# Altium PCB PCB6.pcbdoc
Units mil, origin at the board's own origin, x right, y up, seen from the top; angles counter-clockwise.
Board outline 6080 x 3305 mil, 2 copper layers (Top Layer, Bottom Layer); 30 components, 10 nets, 241 pads, 0 vias.
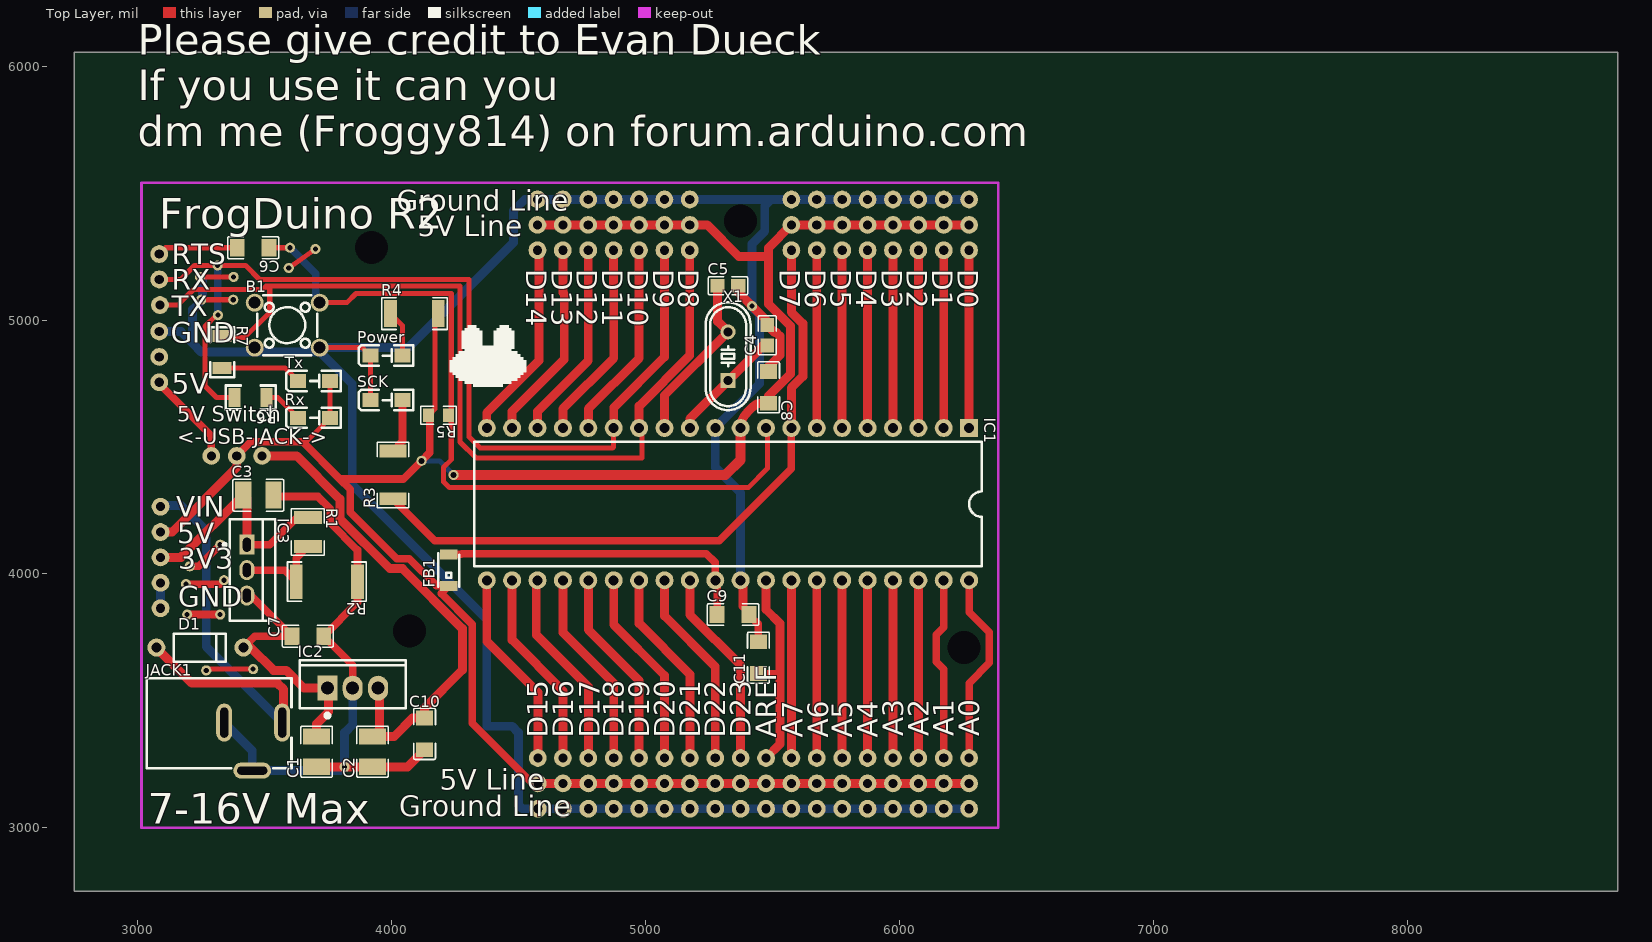
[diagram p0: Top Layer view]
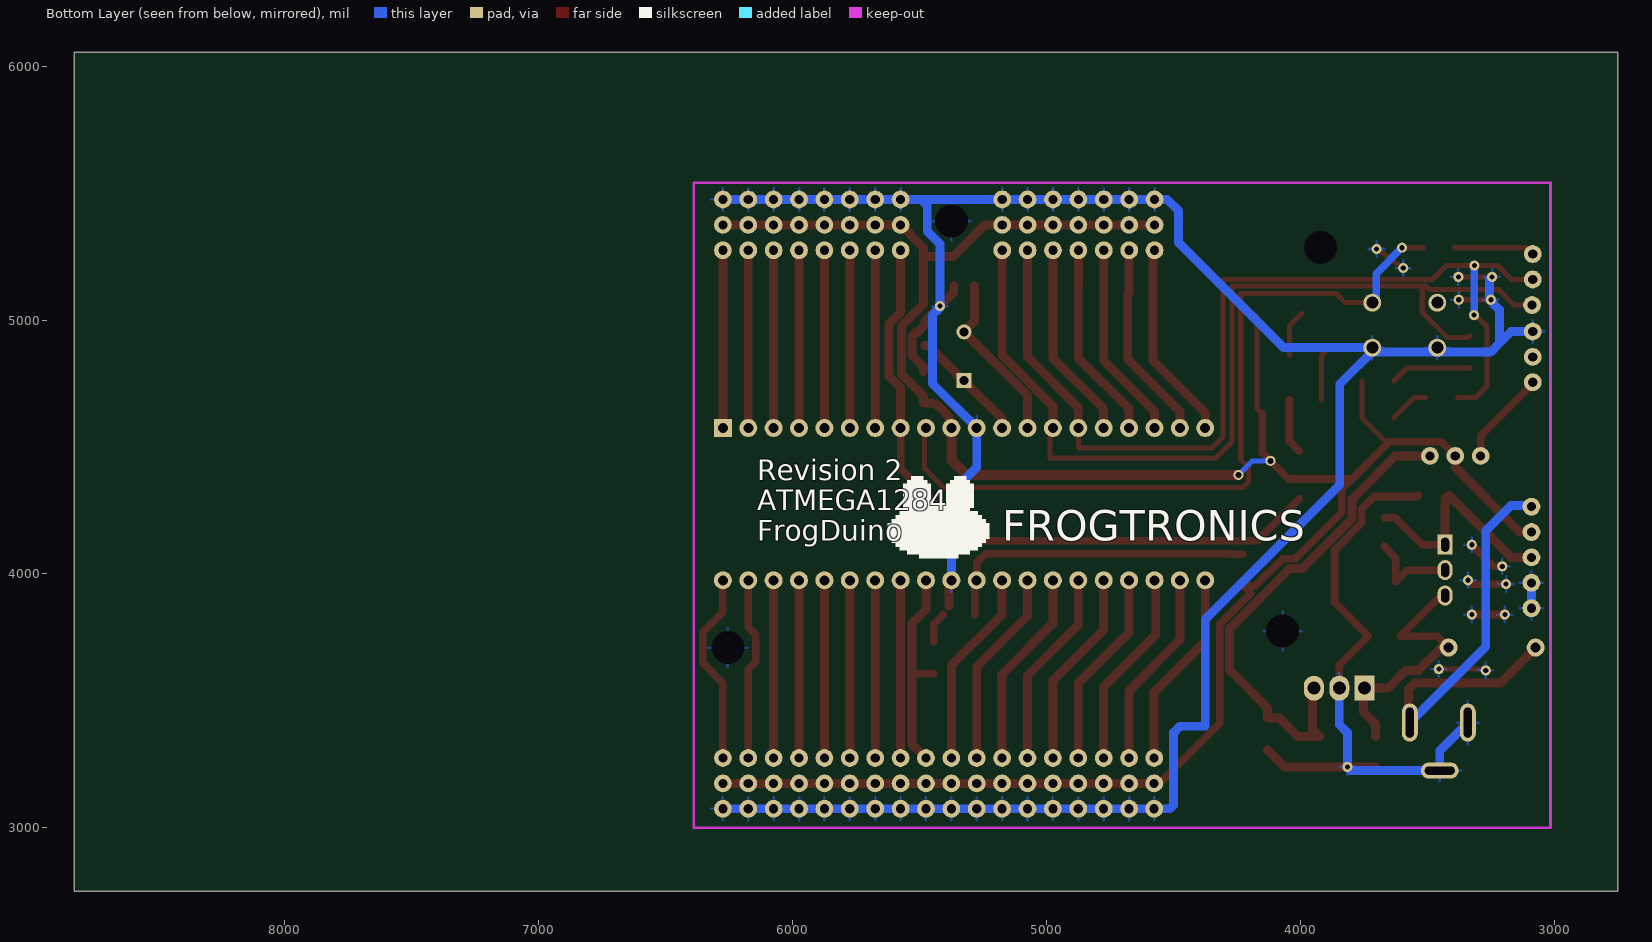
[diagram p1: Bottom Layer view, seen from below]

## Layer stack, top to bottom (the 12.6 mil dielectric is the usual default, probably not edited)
Top Layer: signal copper (thickness not stored)
Dielectric: dielectric 12.6, FR-4, Dk 4.8
Bottom Layer: signal copper (thickness not stored)

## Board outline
8830,2750 2750,2750 2750,6055 8830,6055

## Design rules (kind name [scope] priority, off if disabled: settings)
BoardOutlineClearance copperThickness1oz [All] p0: genericclearance=10 ignorepadtopadclearanceinfootprint=FALSE except(0: Arc-SplitContinuation Track-SplitContinuation SMDPad-SplitContinuation THPad-SplitContinuation Via-SplitContinuation Fill-SplitContinuation Poly-SplitContinuation Region-SplitContinuation Text-SplitContinuation; 6: Track-CutoutEdge SMDPad-CutoutEdge THPad-CutoutEdge Via-CutoutEdge Region-CutoutEdge; 11.8: Track-OutlineEdge SMDPad-OutlineEdge THPad-OutlineEdge Via-OutlineEdge Fill-OutlineEdge Region-OutlineEdge Poly-OutlineEdge Text-OutlineEdge Fill-CutoutEdge)
BoardOutlineClearance copperThickness2oz [All] p0: genericclearance=10 ignorepadtopadclearanceinfootprint=FALSE except(0: Arc-SplitContinuation Track-SplitContinuation SMDPad-SplitContinuation THPad-SplitContinuation Via-SplitContinuation Fill-SplitContinuation Poly-SplitContinuation Region-SplitContinuation Text-SplitContinuation; 6: Track-CutoutEdge SMDPad-CutoutEdge THPad-CutoutEdge Via-CutoutEdge Region-CutoutEdge; 11.8: Track-OutlineEdge SMDPad-OutlineEdge THPad-OutlineEdge Via-OutlineEdge Fill-OutlineEdge Region-OutlineEdge Poly-OutlineEdge Text-OutlineEdge Fill-CutoutEdge)
Clearance copperThickness1oz [(InNet('GROUND') OR InNet('VCC') OR InNet('5VUSB') OR InNet('3V3') OR InNet('XTAL1') OR InNet('XTAL2') OR InNet('AREF') OR InNet('5V') OR InNet('POWER') OR InNet('AVCC'))] p1: gap=7 ignorepadtopadclearanceinfootprint=FALSE except(6: Track-Track Track-SMDPad SMDPad-SMDPad Track-THPad SMDPad-THPad THPad-THPad Track-Via SMDPad-Via THPad-Via Via-Via SMDPad-Fill THPad-Fill Via-Fill Fill-Fill Track-Region SMDPad-Region THPad-Region Via-Region Region-Region Track-Poly SMDPad-Poly THPad-Poly Via-Poly Fill-Poly Region-Poly Poly-Poly Track-Text SMDPad-Text THPad-Text Via-Text Fill-Text Region-Text Poly-Text Text-Text; 6.9: Track-Hole SMDPad-Hole THPad-Hole Via-Hole Fill-Hole Region-Hole Poly-Hole Text-Hole Sheet-Hole; 11.8: Track-Fill Fill-Region Track-Sheet SMDPad-Sheet THPad-Sheet Via-Sheet Fill-Sheet Region-Sheet Poly-Sheet Text-Sheet)
Clearance copperThickness2oz [All] p1: gap=7 ignorepadtopadclearanceinfootprint=FALSE except(6: Track-SMDPad SMDPad-SMDPad Track-THPad SMDPad-THPad THPad-THPad Track-Via SMDPad-Via THPad-Via Via-Via SMDPad-Fill THPad-Fill Via-Fill Fill-Fill Track-Region SMDPad-Region THPad-Region Via-Region Region-Region Track-Poly SMDPad-Poly THPad-Poly Via-Poly Fill-Poly Region-Poly Poly-Poly Track-Text SMDPad-Text THPad-Text Via-Text Fill-Text Region-Text Poly-Text Text-Text; 6.9: Track-Hole SMDPad-Hole THPad-Hole Via-Hole Fill-Hole Region-Hole Poly-Hole Text-Hole Sheet-Hole; 8: Track-Track; 11.8: Track-Fill Fill-Region Track-Sheet SMDPad-Sheet THPad-Sheet Via-Sheet Fill-Sheet Region-Sheet Poly-Sheet Text-Sheet)
DiffPairsRouting differentialPair [All] p1: maxuncoupledlength=10 minlimit=6 maxlimit=6 mostfreqgap=6 toplayer_minwidth=5 toplayer_prefwidth=10 toplayer_maxwidth=100 bottomlayer_minwidth=5 bottomlayer_prefwidth=10 bottomlayer_maxwidth=100
PasteMaskExpansion pasteMaskExpansion [All] p1: expansion=0
PlaneConnect innerPlane [All] p1: planeconnectstyle=Relief reliefexpansion=20 reliefentries=4 reliefconductorwidth=10 reliefairgap=10
PolygonConnect copperRegion [All] p1: connectstyle=Relief reliefentries=4 reliefconductorwidth=10 polygonreliefangle="90 Angle" airgapwidth=10
PolygonConnect copperRegion1 [All] p1: connectstyle=Relief reliefentries=4 reliefconductorwidth=10 polygonreliefangle="90 Angle" airgapwidth=10
PolygonConnect copperRegion2 [All] p1: connectstyle=Relief reliefentries=4 reliefconductorwidth=10 polygonreliefangle="90 Angle" airgapwidth=10
RoutingVias viaSize [All] p1: viastyle="Through Hole" holewidth=20 minholewidth=10 maxholewidth=400 width=40 minwidth=20 maxwidth=600
SolderMaskExpansion solderMaskExpansion [All] p1: useseparateexpansions=TRUE expansion=2 expansionbottom=2
Width copperThickness1oz [All] p1: maxlimit=200 minlimit=10 preferedwidth=20
Width copperThickness2oz [All] p1: maxlimit=100 minlimit=8 preferedwidth=10

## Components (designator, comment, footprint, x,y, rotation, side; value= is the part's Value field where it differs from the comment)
B1 "TS02-66-43-BK-100-SCR-D" SW-TH_4P-L6.0-W6.0-P4.50-LS6.5 3588.99,4979.83 r0 top
C1 "CC1210MKX5R7BB107" C1210 3705,3300 r90 top
C2 "CC1210MKX5R7BB107" C1210 3925,3300 r90 top
C3 "CC1210MKX5R7BB107" C1210 3475,4310 r0 top
C4 "CL21C220JBANNNC" C0805 5480,4940 r90 top
C5 "CL21C220JBANNNC" C0805 5325,5135 r0 top
C6 "1206B104K101CT" C1206 3455,5285 r180 top
C7 "1206B104K101CT" C1206 3670,3755 r180 top
C8 "1206B104K101CT" C1206 5485,4735 r90 top
C9 "1206B104K101CT" C1206 5345,3840 r0 top
C10 "1206B104K101CT" C1206 4130,3370 r90 top
C11 "1206B104K101CT" C1206 5445,3670 r90 top
D1 "1N4007GP-E3/54" DO-41_BD2.4-L4.7-P8.70-D0.9-RD 3245,3710 r180 top
FB1 "2450AT18A100E" ANT-SMD_L3.2-W1.6 4225,4015 r90 top
IC1 "ATMEGA1284-PU" PDIP-40_L52.3-W13.8-P2.54-LS15.2-BL 5325,4275 r180 top
IC2 "LM7805L-TA3-T" TO-220IS_L10.16-W4.7-P2.54-L 3846.95,3550 r0 top
IC3 "LM317T/NOPB" TO-220-3_L10.2-W4.6-P2.54-L 3430,4015 r270 top
JACK1 "694106301002_C5441017" DC-IN-TH_694106301002 3455,3320 r0 top
Power "SML-811UTT86C" LED-SMD_L3.4-W1.3-RD 3980,4860 r0 top
R1 "RC1210FR-07240RL" R1210 3670,4165 r270 top
R2 "CRGP2512F390R" R2512 3745,3970 r180 top
R3 "RC2010JK-07330RL" R2010 4005,4390 r90 top
R4 "RC2010JK-07330RL" R2010 4090,5025 r0 top
R5 "0805W8F1002T5E" R0805 4185,4625 r180 top
R6 "330" R1206 3445,4695 r180 top
R7 "330" R1206 3332.88,4873.95 r270 top
Rx "SML-811UTT86C" LED-SMD_L3.4-W1.3-RD 3695,4615 r0 top
SCK "SML-811UTT86C" LED-SMD_L3.4-W1.3-RD 3980,4685 r0 top
Tx "SML-811UTT86C" LED-SMD_L3.4-W1.3-RD 3695,4760 r0 top
X1 "XIHCELNANF-16MHZ" HC-49US_L11.5-W4.5-P4.88 5325.38,4857.5 r90 top

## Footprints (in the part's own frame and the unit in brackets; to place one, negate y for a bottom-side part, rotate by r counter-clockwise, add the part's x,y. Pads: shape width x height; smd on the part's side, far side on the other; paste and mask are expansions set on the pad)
ANT-SMD_L3.2-W1.6 [mm]
  rect 1x1.75 smd: 1(-1.578,0) 2(1.578,0)
  silkscreen extent -1.68,-1.05 1.68,1.06
C0805 [mm]
  rect 1.41x1.35 smd: 1(-1.03,0) 2(1.03,0)
  silkscreen extent -1.96,-0.9 1.96,0.9
C1206 [mm]
  rect 1.485x1.728 smd: 1(-1.593,0) 2(1.593,0)
  silkscreen extent -2.56,-1.09 2.56,1.09
C1210 [mm]
  rect 1.635x2.7 smd: 1(-1.517,0) 2(1.517,0)
  silkscreen extent -2.56,-1.58 2.56,1.58
DC-IN-TH_694106301002 [mm]
  oval 1.6x3.8 hole 0.8 slot 3 at 90 deg: 1(2.9,2.4)
  oval 1.6x3.8 hole 0.8 slot 3 at 90 deg copper offset 0,0: 2(-2.9,2.4)
  oval 3.8x1.6 hole 0.8 slot 3 at 0 deg: 3(-0.1,-2.4)
  silkscreen extent -10.65,-2.17 3.83,6.84
DO-41_BD2.4-L4.7-P8.70-D0.9-RD [mm]
  round 1.8 hole 1: 1(-4.35,0) 2(4.35,0)
  silkscreen extent -2.6,-1.4 2.6,1.4
HC-49US_L11.5-W4.5-P4.88 [mm]
  rect 1.5x1.5 hole 0.9: 1(-2.44,0)
  round 1.5 hole 0.9: 2(2.44,0)
  silkscreen extent -5.39,-2.25 5.39,2.25
LED-SMD_L3.4-W1.3-RD [mm]
  rect 1.6x1.4 smd: 1(-1.6,0) 2(1.6,0)
  silkscreen extent -2.79,-1.02 2.67,1.02
PDIP-40_L52.3-W13.8-P2.54-LS15.2-BL [mm]
  rect 1.8x1.8 hole 1: 1(-24.13,-7.62)
  round 1.8 hole 1: 2(-21.59,-7.62) 3(-19.05,-7.62) 4(-16.51,-7.62) 5(-13.97,-7.62) 6(-11.43,-7.62) 7(-8.89,-7.62) 8(-6.35,-7.62) 9(-3.81,-7.62) 10(-1.27,-7.62) 11(1.27,-7.62) 12(3.81,-7.62) 13(6.35,-7.62) 14(8.89,-7.62) 15(11.43,-7.62) 16(13.97,-7.62) 17(16.51,-7.62) 18(19.05,-7.62) 19(21.59,-7.62) 20(24.13,-7.62) 21(24.13,7.62) 22(21.59,7.62) 23(19.05,7.62) 24(16.51,7.62) 25(13.97,7.62) 26(11.43,7.62) 27(8.89,7.62) 28(6.35,7.62) 29(3.81,7.62) 30(1.27,7.62) 31(-1.27,7.62) 32(-3.81,7.62) 33(-6.35,7.62) 34(-8.89,7.62) 35(-11.43,7.62) 36(-13.97,7.62) 37(-16.51,7.62) 38(-19.05,7.62) 39(-21.59,7.62) 40(-24.13,7.62)
  silkscreen extent -25.4,-6.22 25.4,6.22
R0805 [mm]
  rect 1.133x1.377 smd: 1(-1,0) 2(1,0)
  silkscreen extent -1.76,-0.92 1.76,0.92
R1206 [mm]
  rect 1.2x1.9 smd: 1(-1.6,0) 2(1.6,0)
  silkscreen extent -2.5,-1.2 2.5,1.2
R1210 [mil]
  rect 50.49x110.55 smd: 1(-56.74,0) 2(56.74,0)
  silkscreen extent -91,-64 91,64
R2010 [mm]
  rect 1.283x2.7 smd: 1(-2.391,0) 2(2.391,0)
  silkscreen extent -3.26,-1.58 3.26,1.58
R2512 [mil]
  rect 50.49x136.06 smd: 1(-120.72,0) 2(120.72,0)
  silkscreen extent -155,-77 155,77
SW-TH_4P-L6.0-W6.0-P4.50-LS6.5 [mm]
  round 1.8 hole 1.2: 1(-3.25,2.25) 2(3.25,2.25) 3(-3.25,-2.25) 4(3.25,-2.25)
  silkscreen extent -3,-3 3,3
TO-220-3_L10.2-W4.6-P2.54-L [mm]
  rect 2x1.5 hole 0.8 slot 1.4 at 0 deg: 1(-2.54,0)
  oval 2x1.5 hole 0.8 slot 1.4 at 0 deg: 2(0,0) 3(2.54,0)
  silkscreen extent -5.08,-2.37 5.08,2.86
TO-220IS_L10.16-W4.7-P2.54-L [mm]
  rect 2x2.5 hole 1.3: 1(-2.54,0)
  oval 2x2.5 hole 1.3: 2(0,0) 3(2.54,0)
  silkscreen extent -5.3,-2.94 5.3,2.8

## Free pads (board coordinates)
  round 70 hole 36: 1(3085,4755) 1(3490,4465) 1(5475,3075) 1(5475,3175) 1(5475,3275) 1(5575,3075) 1(5575,3175) 1(5575,3275) 1(6275,5274.99) 1(6275,5374.99) 1(6275,5474.99) 2(3390,4465) 2(5375,3075) 2(5375,3175) 2(5375,3275) 2(5675,3075) 2(5675,3175) 2(5675,3275) 2(6175,5274.99) 2(6175,5374.99) 2(6175,5474.99) 3(3290,4465) 3(5275,3075) 3(5275,3175) 3(5275,3275) 3(5775,3075) 3(5775,3175) 3(5775,3275) 3(6075,5274.99) 3(6075,5374.99) 3(6075,5474.99) 3V3(3090,4065) 4(5175,3075) 4(5175,3175) 4(5175,3275) 4(5875,3075) 4(5875,3175) 4(5875,3275) 4(5975,5274.99) 4(5975,5374.99) 4(5975,5474.99) 5(5075,3075) 5(5075,3175) 5(5075,3275) 5(5875,5274.99) 5(5875,5374.99) 5(5875,5474.99) 5(5975,3075) 5(5975,3175) 5(5975,3275) 5V(3090,4165) 6(4975,3075) 6(4975,3175) 6(4975,3275) 6(5775,5274.99) 6(5775,5374.99) 6(5775,5474.99) 6(6075,3075) 6(6075,3175) 6(6075,3275) 7(4875,3075) 7(4875,3175) 7(4875,3275) 7(5675,5274.99) 7(5675,5374.99) 7(5675,5474.99) 7(6175,3075) 7(6175,3175) 7(6175,3275) 8(4775,3075) 8(4775,3175) 8(4775,3275) 8(5575,5274.99) 8(5575,5374.99) 8(5575,5474.99) 8(6275,3075) 8(6275,3175) 8(6275,3275) 9(4576.1,3075) 9(4576.1,3175) 9(4576.1,3275) 9(4675,3075) 9(4675,3175) 9(4675,3275) 9(5174.6,5275) 9(5174.6,5375) 9(5174.6,5475) 10(5074.6,5275) 10(5074.6,5375) 10(5074.6,5475) 11(4974.6,5275) 11(4974.6,5375) 11(4974.6,5475) 12(4874.6,5275) 12(4874.6,5375) 12(4874.6,5475) 13(4774.6,5275) 13(4774.6,5375) 13(4774.6,5475) 14(4674.6,5275) 14(4674.6,5375) 14(4674.6,5475) 15(4574.6,5275) 15(4574.6,5375) 15(4574.6,5475) GND(3085,4955) GND(3090,3865) GND(3090,3965) NC(3085,4855) RTS(3085,5260) RX(3085,5160) TX(3087.7,5059.21) VIN(3090,4265)
  round 0.1 hole 130: 1(3920,5285) 1(4070,3775) 1(5375,5390) 1(6255,3710)
  round 40 hole 20: TP1(3190,3960) TP1(3195,3840) TP1(3205,4030) TP1(3245,5170) TP1(3250,5080) TP1(3270,3620) TP1(3315,5214.88) TP1(3315.98,5019.21) TP1(3325,4115) TP1(3325,3840) TP1(3340,3975) TP1(3376.34,5080) TP1(3377.92,5170) TP1(3455,3625) TP1(3595,5205) TP1(3600,5285) TP1(3700,5280) TP1(3815,3240) TP1(5420,5055)
  round 40 hole 24: TP3(4244.24,4390) TP4(4118.26,4445.59)

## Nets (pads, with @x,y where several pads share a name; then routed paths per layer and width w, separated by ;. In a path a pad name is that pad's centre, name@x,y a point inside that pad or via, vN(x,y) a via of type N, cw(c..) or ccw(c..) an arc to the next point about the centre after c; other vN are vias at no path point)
3V3: C3.1 IC3.1 pad.3V3 R1.1 | length 912.1
  Top Layer w30: IC3.1 3520,4115 3626.74,4221.74 R1.1
  Top Layer w35: pad.3V3 3170.26,4065 C3.1 3430.01,4295.26 IC3.1
5V: C2.2 C10.2 IC2.3 pad.1@3490,4465 | length 1966.4
  Top Layer w35: pad.1@3490,4465 3626.42,4465 3796.5,4294.92 3796.5,4217.84 3992.84,4021.5 4042.34,4021.5 4279,3784.84 4279,3621.7 4130,3472.7 C10.2 4082.7,3432.7 4009.74,3359.74 C2.2 3951.95,3386.69 IC2.3@3951.95,3550
5VUSB: pad.1@3085,4755 pad.3@3290,4465 | length 374.9
  Top Layer w30: pad.1@3085,4755 3085,4750 3290,4545 pad.3@3290,4465
AREF: C11.1 IC1.32 pad.1@5475,3275 | length 828.6
  Top Layer w30: C11.1 5525.97,3607.3 5530.61,3602.66
  Top Layer w35: pad.1@5475,3275 5530.61,3330.61 5530.61,3602.66 5530.61,3804.39 5475,3860 IC1.32@5475,3970
AVCC: C9.1 FB1.2 IC1.30 | length 1273.7
  Top Layer w30: FB1.2 4273.85,4077.13 4276.72,4080 5239.99,4080 5274.99,4045 IC1.30 5282.3,3967.7 C9.1
GROUND: B1.3 B1.4 C1.1 C2.1 C3.2 C4.2 C5.2 C7.1 C8.2 C9.2 C10.1 C11.2 IC1.11 IC1.31 IC2.2 JACK1.2 JACK1.3 pad.1@4070,3775 pad.1@5375,5390 pad.1@5475,3075 pad.1@5575,3075 pad.1@6255,3710 pad.1@6275,5474.99 pad.2@5375,3075 pad.2@5675,3075 pad.2@6175,5474.99 pad.3@5275,3075 pad.3@5775,3075 pad.3@6075,5474.99 pad.4@5175,3075 pad.4@5875,3075 pad.4@5975,5474.99 pad.5@5075,3075 pad.5@5875,5474.99 pad.5@5975,3075 pad.6@4975,3075 pad.6@5775,5474.99 pad.6@6075,3075 pad.7@4875,3075 pad.7@5675,5474.99 pad.7@6175,3075 pad.8@4775,3075 pad.8@5575,5474.99 pad.8@6275,3075 pad.9@4576.1,3075 pad.9@4675,3075 pad.9@5174.6,5475 pad.10@5074.6,5475 pad.11@4974.6,5475 pad.12@4874.6,5475 pad.13@4774.6,5475 pad.14@4674.6,5475 pad.15@4574.6,5475 pad.GND pad.TP1@3190,3960 pad.TP1@3195,3840 pad.TP1@3205,4030 pad.TP1@3245,5170 pad.TP1@3250,5080 pad.TP1@3270,3620 pad.TP1@3325,3840 pad.TP1@3325,4115 pad.TP1@3340,3975 pad.TP1@3376.34,5080 pad.TP1@3377.92,5170 pad.TP1@3455,3625 pad.TP1@3595,5205 pad.TP1@3700,5280 pad.TP1@3815,3240 pad.TP1@5420,5055 Power.1 R2.1 SCK.1 | length 14094.3
  Top Layer w20: pad.TP1@3245,5170 pad.TP1@3372.92,5170 ; pad.TP1@3255,5080 pad.TP1@3366.34,5080 ; pad.TP1@3270,3620 3275,3625 pad.TP1@3455,3625 ; pad.TP1@3595,5205 pad.TP1@3700,5280 ; B1.4@3701.94,4891.25 3885.76,4891.25 Power.1 SCK.1
  Top Layer w30: pad.TP1@3190,3960 3325,3960 pad.TP1@3340,3975 ; pad.TP1@3195,3840 pad.TP1@3325,3840 ; pad.TP1@3210,4030 3240,4030 pad.TP1@3325,4115 ; C3.2 3539.74,4305 3710,4305 3758,4257 3758,4201.89 3865.72,4094.17 R2.1 3865.72,3888.02 C7.1 3846.95,3640.75 IC2.2 ; C9.2 5445,3802.7 C11.2
  Top Layer w35: C1.1 C2.1 4062.96,3240.26 C10.1 ; C5.2 5365.55,5109.45 5420,5055 5480,4995 C4.2 5509.86,4950.69 5516.3,4950.69 5530.06,4936.93 5530.06,4861.97 5485,4816.91 C8.2 ; IC1.31 5385,3965 C9.2@5385,3872.7
  Bottom Layer w35: pad.GND@3080,4955 3170,4955 3216.05,4908.95 ; pad.GND@3090,3865 pad.GND@3090,3965 ; pad.TP1@3245,5170 3255,5160 3255,5080 3216.05,5041.05 3216.05,4908.95 ; JACK1.2 3451.06,3304.26 JACK1.3 3800.51,3225.51 3815,3240 3815,3375 3846.95,3406.95 IC2.2 ; B1.4@3712.31,4873.95 3251.05,4873.95 3216.05,4908.95 ; IC1.31 5374.99,4320.01 5274.99,4420.01 IC1.11 5450,4750.01 5450,5020 pad.TP1@5417.5,5052.5 ; pad.TP1@5420,5055 5420,5300 5470,5350 5470,5450.24 5494.75,5474.99 ; pad.8@6275,3075 6175,3075 6075,3075 5975,3075 5875,3075 5775,3075 5675,3075 5575,3075 5475,3075 5375,3075 5275,3075 5175,3075 5075,3075 4975,3075 4875,3075 4775,3075 4675,3075 4576.1,3075 4515.18,3075 4499.75,3090.43 4499.75,3375.25 4475,3400 4375,3400 4375,3821.68 3845,4351.68 3845,4748.19 3701.94,4891.25 4066.25,4891.25 4480,5305 4480,5430 4525,5475 4574.6,5475 4674.6,5474.99 4774.6,5474.99 4874.6,5474.99 4974.6,5474.99 5074.6,5474.99 5174.6,5474.99 5494.75,5474.99 ; pad.1@6275,5474.99 6175,5474.99 6075,5474.99 5975,5474.99 5875,5474.99 5775,5474.99 5675,5474.99 5575,5474.99 5494.75,5474.99
POWER: Power.2 R4.1 | length 184.5
  Top Layer w20: R4.1 4042.99,4977.87 Power.2
VCC: C8.1 FB1.1 IC1.10 pad.1@5475,3175 pad.1@5575,3175 pad.1@6275,5374.99 pad.2@3390,4465 pad.2@5375,3175 pad.2@5675,3175 pad.2@6175,5374.99 pad.3@5275,3175 pad.3@5775,3175 pad.3@6075,5374.99 pad.4@5175,3175 pad.4@5875,3175 pad.4@5975,5374.99 pad.5@5075,3175 pad.5@5875,5374.99 pad.5@5975,3175 pad.5V pad.6@4975,3175 pad.6@5775,5374.99 pad.6@6075,3175 pad.7@4875,3175 pad.7@5675,5374.99 pad.7@6175,3175 pad.8@4775,3175 pad.8@5575,5374.99 pad.8@6275,3175 pad.9@4576.1,3175 pad.9@4675,3175 pad.9@5174.6,5375 pad.10@5074.6,5375 pad.11@4974.6,5375 pad.12@4874.6,5375 pad.13@4774.6,5375 pad.14@4674.6,5375 pad.15@4574.6,5375 pad.TP3 pad.TP4 R4.2 R5.2 Rx.2 Tx.2 | length 9578
  Top Layer w20: 3649.64,4520.98 3663.97,4520.98 Rx.2 Tx.2 ; R5.2 4150.96,4630.33 4170.96,4650.33 4170.96,5011.82 R4.2
  Top Layer w30: pad.2@3390,4465 3445.98,4520.98 3649.64,4520.98 3796.81,4373.81 ; R5.2@4150.96,4630.33 4150.96,4478.29 pad.TP4 4046.48,4373.81 3796.81,4373.81 ; 4317.5,3412.5 4555,3175 pad.9@4576.1,3175 ; 4317.5,3417.5 4317.5,3800.78 4195.21,3923.08 FB1.1 4177.13,3952.87 4070,4060 4020,4060 3836.88,4243.12 3836.88,4333.74 3796.81,4373.81
  Top Layer w35: pad.5V 3135,4165 3390,4420 pad.2@3390,4465 ; pad.15@4574.6,5375 4674.6,5375 4774.6,5375 4874.6,5375 4974.6,5375 5074.6,5375 5174.6,5375 5243.49,5375 5368.5,5250 5483.99,5249.99 5485,5248.98 ; pad.9@4576.1,3175 4675,3175 4775,3175 4875,3175 4975,3175 5075,3175 5175,3175 5275,3175 5375,3175 5475,3175 5575,3175 5675,3175 5775,3175 5875,3175 5975,3175 6075,3175 6175,3175 pad.8@6275,3175 ; IC1.10 cw(c5459.48,4575) 5399.74,4634.74 5425,4660 cw(c5454.69,4630.31) 5454.69,4672.3 C8.1 5485,4701.24 5571.06,4787.3 5571.06,4977.03 5485,5063.09 5485,5248.98 ; pad.1@6275,5374.99 6175,5374.99 6075,5374.99 5975,5374.99 5875,5374.99 5775,5374.99 5675,5374.99 5575,5374.99 5485,5284.99 5485,5248.98
  Top Layer w40: pad.TP3 5314.99,4390 5374.99,4450 IC1.10
  Bottom Layer w20: pad.TP4 4188.65,4445.59 pad.TP3
XTAL1: C5.1 IC1.13 X1.2 | length 680.7
  Top Layer w35: IC1.13 5074.99,4703.17 X1.2 5284.45,4994.49 C5.1
XTAL2: C4.1 IC1.12 X1.1 | length 460.5
  Top Layer w35: IC1.12 5174.99,4611.05 X1.1 5463.39,4899.45 C4.1
pads on no net: B1.1 B1.2 C1.2 C6.1 C6.2 C7.2 D1.1 D1.2 IC1.1 IC1.2 IC1.3 IC1.4 IC1.5 IC1.6 IC1.7 IC1.8 IC1.9 IC1.14 IC1.15 IC1.16 IC1.17 IC1.18 IC1.19 IC1.20 IC1.21 IC1.22 IC1.23 IC1.24 IC1.25 IC1.26 IC1.27 IC1.28 IC1.29 IC1.33 IC1.34 IC1.35 IC1.36 IC1.37 IC1.38 IC1.39 IC1.40 IC2.1 IC3.2 IC3.3 JACK1.1 R1.2 R2.2 R3.1 R3.2 R5.1 R6.1 R6.2 R7.1 R7.2 Rx.1 SCK.2 Tx.1
copper on no net: | length 39291
  Top Layer w20: 3085,5160 3169.11,5160 3223.99,5214.88 3315,5214.88 3425.12,5214.88 3480,5160 4305,5160 4305,4540 4349.14,4495.86 4870.86,4495.86 4874.99,4499.99 4874.99,4575 ; 3085,5260 3110,5285 3392.3,5285 ; 3087.7,5059.21 3088.49,5060 3160,5060 3220,5120 3492.23,5120 3506.24,5134.02 ; 3315.98,5019.21 3309.21,5019.21 3265,4975 3265,4740 3310,4695 3382.01,4695 ; 3332.88,4810.96 3581.05,4810.96 3632.01,4760 ; 3332.88,4936.95 3337.88,4931.95 3421.95,4931.95 3520,5030 3520,5120.26 3506.24,5134.02 ; 3508,4695 3552.01,4695 3632.01,4615 ; 3517.7,5285 3600,5285 ; 3701.94,5068.41 3823.41,5068.41 3860,5105 4235,5105 4235,4450 4205,4420 4205,4363.24 4228.24,4340 5405,4340 5479.99,4414.99 5479.99,4570 5474.99,4575 ; 4974.99,4575 4985.86,4564.13 4985.86,4455.86 4334.14,4455.86 4270,4520 4270,5134.02 3506.24,5134.02
  Top Layer w30: 3416.26,3710 3461.26,3755 3607.3,3755 3447.3,3915 3429.99,3915 ; 3429.99,4015 3579.28,4015 3624.28,3970 3624.28,4062.54 3670,4108.26 ; 4005,4295.86 4170.86,4130 5290,4130 5574.99,4414.99 5574.99,4575 ; 4005,4484.14 4042.99,4522.13 4042.99,4685 ; 6175,3275 6175,3620 ; 6175,3625 6145,3655 6145,3760 6175,3790 6175,3975 ; 6274.99,3275.01 6274.99,3564.99 ; 6274.99,3569.99 6355,3650 6355,3770 6274.99,3850.01 6274.99,3975
  Top Layer w35: 3073.74,3710 3213.74,3570 3550,3570 3574.75,3545.25 3574.75,3420.07 3569.17,3414.49 ; 3416.26,3710 3445.5,3710 3535.5,3620 3585,3620 3655,3550 3751.95,3550 3751.95,3456.95 3705,3410 3705,3359.74 ; 4375,3975 4375,3735 4576.1,3533.9 ; 4375,4575 4375,4635 4580,4840 4580,5269.6 4574.6,5275 ; 4475,3975 4475,3740 4675,3540 ; 4475,4575 4475,4640 4680,4845 4680,5103.69 4674.6,5109.09 4674.6,5275 ; 4574.99,3975 4570,3970.01 4570,3760 4775,3555 ; 4574.99,4575 4574.99,4639.99 4774.6,4839.6 4774.6,5275 ; 4576.1,3275 4576.1,3528.9 ; 4675,3275 4675,3535 ; 4674.99,3975 4674.99,3770.01 4875,3570 ; 4674.99,4575 4674.99,4649.99 4875,4850 4875,5137.66 4874.6,5138.06 4874.6,5275 ; 4775,3275 4775,3550 ; 4774.99,3975 4774.99,3780.01 4975,3580 ; 4774.99,4575 4774.99,4649.99 4975,4850 4975,5274.6 4974.6,5275 ; 4875,3275 4875,3565 ; 4874.99,3975 4874.99,3800.01 5075,3600 ; 4874.99,4575 4874.99,4654.99 5074.6,4854.6 5074.6,5275 ; 4975,3275 4975,3575 ; 4975,3975 4975,3805 5175,3605 ; 4975,4575.01 4975,4661.16 5174.6,4860.76 5174.6,5275 ; 5075,3275 5075,3595 ; 5074.99,3975 5074.99,3835.01 5275,3635 ; 5175,3275 5175,3600 ; 5174.99,3975 5174.99,3840.01 5375,3640 ; 5275,3275 5275,3630 ; 5375,3275 5375,3635 ; 5574.99,3275.01 5574.99,3970 ; 5574.99,4575 5574.99,4733.25 5620,4778.26 5620,4986.08 5574.99,5031.08 5574.99,5274.98 ; 5675,3275 5675,3970 ; 5674.99,4575 5674.99,5274.98 ; 5775,3275 5775,3970 ; 5774.99,4575 5775,5274.99 ; 5875,3275 5875,3970 ; 5874.99,4575 5874.99,5274.99 ; 5974.99,3275.01 5974.99,3970 ; 5974.99,4575 5974.99,5274.99 ; 6074.99,3275.01 6074.99,3970 ; 6074.99,4575 6074.99,5274.99 ; 6174.99,4575 6174.99,5274.99 ; 6274.99,4575 6274.99,5274.99
  Bottom Layer w30: 3315,5214.88 3315,5020.19 3315.98,5019.21 ; 3600,5285 3701.94,5183.06 3701.94,5068.41
  Bottom Layer w35: 3090,4265 3094.75,4269.75 3170.25,4269.75 3270,4170 3270,3713.66 3569.17,3414.49

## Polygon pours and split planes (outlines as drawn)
GROUND on Bottom Layer (solid, remove dead copper, pour order 0): 6400,3000 3030,3000 3030,5540 6400,5540

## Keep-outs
Board Outline Layer:
  lines w10: 3015,3000 6390,3000 6390,5540 3015,5540 3015,3000

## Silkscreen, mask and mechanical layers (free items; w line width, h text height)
Top Silkscreen Layer:
  drawing of 4 lines, arcs and shapes, not listed
  text "Please give credit to Evan Dueck / If you use it can you / dm me (Froggy814) on forum.arduino.com" at 3000,5685 h120
  text "Ground Line" at 4020,5430 h80
  text "FrogDuino R2" at 3085,5360 h120
  text "5V Line" at 4103.4,5330 h80
  text "RTS" at 3134.78,5220 h80
  text "D14" at 4530,5200 h80 r270
  text "D13" at 4630,5200 h80 r270
  text "D12" at 4730,5200 h80 r270
  text "D11" at 4830,5200 h80 r270
  text "D10" at 4930,5200 h80 r270
  text "D9" at 5030,5200 h80 r270
  text "D8" at 5130,5200 h80 r270
  text "D7" at 5530,5200 h80 r270
  text "D6" at 5630,5200 h80 r270
  text "D5" at 5730,5200 h80 r270
  text "D4" at 5830,5200 h80 r270
  text "D3" at 5930,5200 h80 r270
  text "D2" at 6030,5200 h80 r270
  text "D1" at 6130,5200 h80 r270
  text "D0" at 6230,5200 h80 r270
  text "RX" at 3135,5120 h80
  text "TX" at 3135,5015 h80
  text "GND" at 3130,4910 h80
  text "5V" at 3135,4710 h80
  text "5V Switch / <-USB-JACK->" at 3155,4510 h60
  text "VIN" at 3151.9,4225 h80
  text "5V" at 3155,4120 h80
  text "3V3" at 3160,4020 h80
  text "GND" at 3158.8,3870 h80
  text "A3" at 6015,3360 h80 r90
  text "A2" at 6115,3360 h80 r90
  text "A1" at 6215,3360 h80 r90
  text "A0" at 6315,3360 h80 r90
  text "D15" at 4615,3355 h80 r90
  text "D16" at 4715,3355 h80 r90
  text "D17" at 4820,3355 h80 r90
  text "D18" at 4915,3355 h80 r90
  text "D19" at 5015,3355 h80 r90
  text "D20" at 5115,3355 h80 r90
  text "D21" at 5215,3355 h80 r90
  text "D22" at 5315,3355 h80 r90
  text "D23" at 5415,3355 h80 r90
  text "AREF" at 5515,3354.95 h80 r90
  text "A7" at 5620,3355 h80 r90
  text "A6" at 5720,3355 h80 r90
  text "A5" at 5815,3355 h80 r90
  text "A4" at 5915,3355 h80 r90
  text "5V Line" at 4190,3150 h80
  text "Ground Line" at 4030,3045 h80
  text "7-16V Max" at 3040,3015 h120
Bottom Silkscreen Layer:
  drawing of 4 lines, arcs and shapes, not listed
  text "FROGTRONICS" at 5175,4130 h120
  text "Revision 2 / ATMEGA1284 / FrogDuino" at 6140,4130 h80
